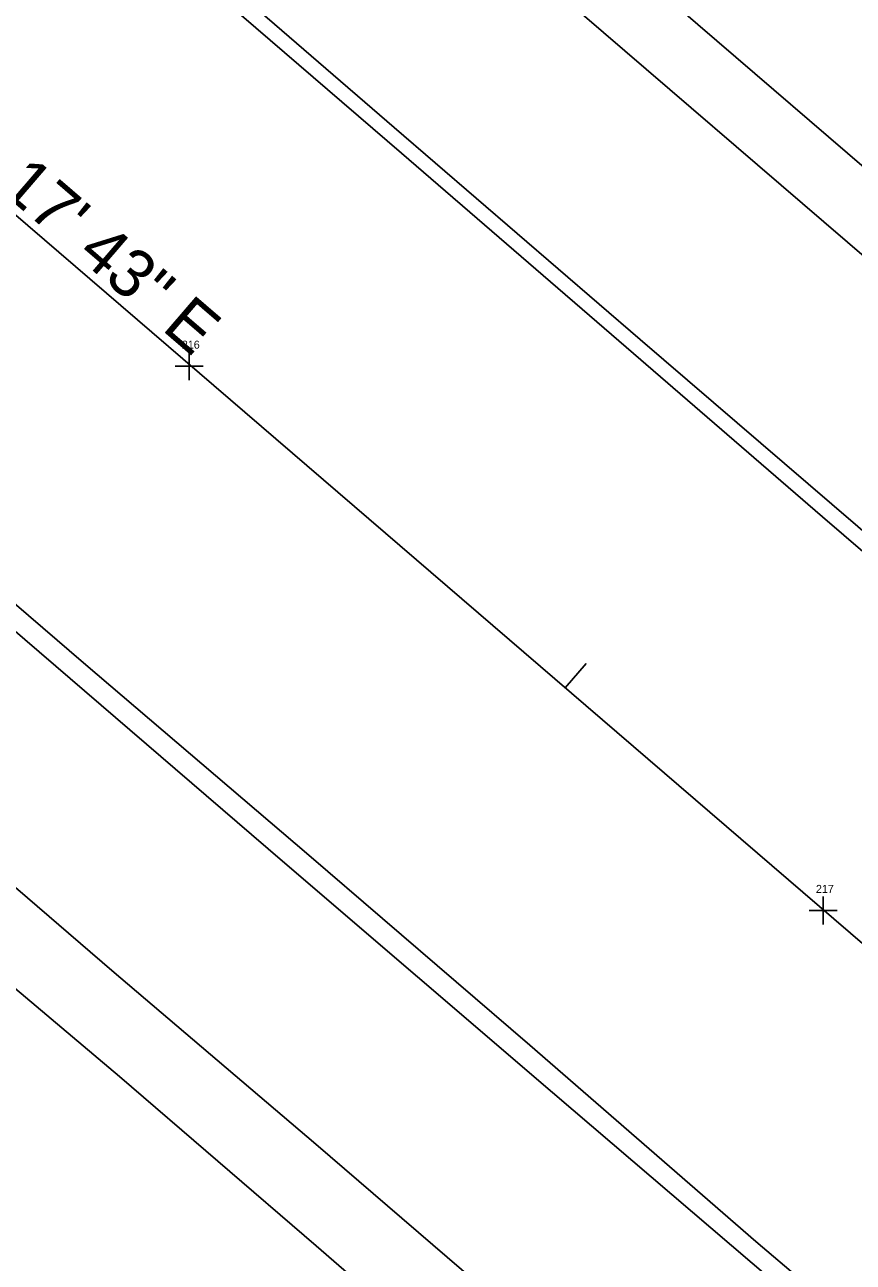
# Model space of a CAD drawing. Extents: x 2076109 to 2080761, y 592812 to 596750.
# Drawn here: x 2076795.1 to 2076898.6, y 596092.9 to 596247.5 of the extents above; entities that cross this region are included whole.
import ezdxf

# ---------------------------------------------------------------- set-up
doc = ezdxf.new("R2010")
doc.units = 0
for name, color, linetype in [('Default', 7, 'Continuous'), ('RD_EX_Misc', 7, 'Continuous'), ('RD_EX_Road', 7, 'Continuous'), ('RD_HC_Cl', 7, 'Continuous'), ('RD_HC_Data', 7, 'Continuous'), ('RD_HC_Data_Tic', 7, 'Continuous')]:
    doc.layers.add(name, color=color, linetype=linetype)

msp = doc.modelspace()

# ---------------------------------------------------------------- linework, layer by layer
at = {"layer": 'Default'}
for p, q in [((2076815.68, 596206.58), (2076815.68, 596203.08)), ((2076815.68, 596206.58), (2076815.68, 596203.08)), ((2076817.43, 596204.83), (2076813.93, 596204.83)), ((2076817.43, 596204.83), (2076813.93, 596204.83)), ((2076894.88, 596138.59), (2076894.88, 596135.09)), ((2076894.88, 596138.59), (2076894.88, 596135.09)), ((2076896.63, 596136.84), (2076893.13, 596136.84)), ((2076896.63, 596136.84), (2076893.13, 596136.84))]:
    msp.add_line(p, q, dxfattribs=at)
at = {"layer": 'RD_EX_Misc'}
for points in [[(2076810.47, 596295.64), (2076861.8, 596251.39), (2076900.57, 596218.06), (2076940.76, 596183.48), (2076983.39, 596147), (2077038.07, 596099.91), (2077086.97, 596057.78), (2077132.28, 596018.8), (2077181.85, 595976.05), (2077229.69, 595934.91), (2077274.19, 595896.66), (2077329.2, 595849.52), (2077358.6, 595824.22)], [(2076810.47, 596295.64), (2076861.8, 596251.39), (2076900.57, 596218.06), (2076940.76, 596183.48), (2076983.39, 596147), (2077038.07, 596099.91), (2077086.97, 596057.78), (2077132.28, 596018.8), (2077181.85, 595976.05), (2077229.69, 595934.91), (2077274.19, 595896.66), (2077329.2, 595849.52), (2077358.6, 595824.22)], [(2077334.93, 595810.96), (2077327.55, 595817.3), (2077300.53, 595840.37), (2077267.76, 595868.37), (2077240.07, 595892.05), (2077211.41, 595916.6), (2077178.43, 595944.97), (2077142.26, 595976.09), (2077108.47, 596005.28), (2077069.23, 596038.87), (2077039.16, 596064.68), (2077006.35, 596092.75), (2076967.21, 596126.45), (2076935.59, 596153.65), (2076905.14, 596179.73), (2076872.01, 596208.18), (2076841.3, 596234.65), (2076810.18, 596261.57), (2076792.25, 596277.09)], [(2077334.93, 595810.96), (2077327.55, 595817.3), (2077300.53, 595840.37), (2077267.76, 595868.37), (2077240.07, 595892.05), (2077211.41, 595916.6), (2077178.43, 595944.97), (2077142.26, 595976.09), (2077108.47, 596005.28), (2077069.23, 596038.87), (2077039.16, 596064.68), (2077006.35, 596092.75), (2076967.21, 596126.45), (2076935.59, 596153.65), (2076905.14, 596179.73), (2076872.01, 596208.18), (2076841.3, 596234.65), (2076810.18, 596261.57), (2076792.25, 596277.09)], [(2076740.94, 596217.33), (2076779.88, 596183.77), (2076827.32, 596143.01), (2076861.06, 596114.09), (2076898.34, 596082.26), (2076930.17, 596054.83), (2076977.99, 596013.66), (2077013.1, 595983.67), (2077050.75, 595951.15), (2077080.28, 595925.68), (2077141.22, 595873.03), (2077167.07, 595850.5), (2077217.75, 595806.94), (2077236.47, 595790.71), (2077261.03, 595769.53)], [(2076740.94, 596217.33), (2076779.88, 596183.77), (2076827.32, 596143.01), (2076861.06, 596114.09), (2076898.34, 596082.26), (2076930.17, 596054.83), (2076977.99, 596013.66), (2077013.1, 595983.67), (2077050.75, 595951.15), (2077080.28, 595925.68), (2077141.22, 595873.03), (2077167.07, 595850.5), (2077217.75, 595806.94), (2077236.47, 595790.71), (2077261.03, 595769.53)], [(2077238.94, 595757.09), (2077227.22, 595767.31), (2077200.97, 595789.86), (2077174.3, 595812.85), (2077143.56, 595839.45), (2077119.23, 595860.41), (2077093.27, 595882.76), (2077072.46, 595900.64), (2077047.17, 595922.37), (2077020.07, 595945.55), (2076995.16, 595967.19), (2076973.2, 595985.95), (2076950.94, 596005.11), (2076925.46, 596027.1), (2076903.87, 596045.6), (2076877.62, 596068.1), (2076855.08, 596087.36), (2076831.5, 596107.64), (2076806.02, 596129.35), (2076775.58, 596155.55), (2076743.51, 596183.09), (2076721.01, 596202.46)], [(2077238.94, 595757.09), (2077227.22, 595767.31), (2077200.97, 595789.86), (2077174.3, 595812.85), (2077143.56, 595839.45), (2077119.23, 595860.41), (2077093.27, 595882.76), (2077072.46, 595900.64), (2077047.17, 595922.37), (2077020.07, 595945.55), (2076995.16, 595967.19), (2076973.2, 595985.95), (2076950.94, 596005.11), (2076925.46, 596027.1), (2076903.87, 596045.6), (2076877.62, 596068.1), (2076855.08, 596087.36), (2076831.5, 596107.64), (2076806.02, 596129.35), (2076775.58, 596155.55), (2076743.51, 596183.09), (2076721.01, 596202.46)]]:
    msp.add_lwpolyline(points, dxfattribs=at)
at = {"layer": 'RD_EX_Road'}
for points in [[(2077309.59, 595877.22), (2077282.74, 595900.37), (2077256.36, 595923.26), (2077227.25, 595948.47), (2077198.79, 595972.87), (2077175.8, 595992.64), (2077153.37, 596012.36), (2077130.64, 596031.73), (2077105.62, 596053.51), (2077080.49, 596075.06), (2077051.54, 596099.91), (2077024.4, 596123.26), (2077002.19, 596142.32), (2076978.91, 596162.67), (2076952.21, 596185.24), (2076929.19, 596204.76), (2076902.69, 596227.39), (2076879.24, 596247.55), (2076859.1, 596264.86), (2076833.46, 596286.99), (2076816.41, 596301.99)], [(2077309.59, 595877.22), (2077282.74, 595900.37), (2077256.36, 595923.26), (2077227.25, 595948.47), (2077198.79, 595972.87), (2077175.8, 595992.64), (2077153.37, 596012.36), (2077130.64, 596031.73), (2077105.62, 596053.51), (2077080.49, 596075.06), (2077051.54, 596099.91), (2077024.4, 596123.26), (2077002.19, 596142.32), (2076978.91, 596162.67), (2076952.21, 596185.24), (2076929.19, 596204.76), (2076902.69, 596227.39), (2076879.24, 596247.55), (2076859.1, 596264.86), (2076833.46, 596286.99), (2076816.41, 596301.99)], [(2076790.96, 596275.94), (2076814.77, 596255.12), (2076842.21, 596231.47), (2076870.29, 596207.22), (2076894.79, 596186.02), (2076920.29, 596164.11), (2076947.36, 596141.05), (2076969.17, 596122), (2076994.72, 596100.04), (2077020.61, 596077.66), (2077049.58, 596053.31), (2077078.66, 596028.07), (2077094.19, 596014.5), (2077117.9, 595994.16), (2077143.78, 595971.83), (2077167.12, 595951.98), (2077186.93, 595934.87), (2077205.77, 595918.84), (2077227.43, 595900.11), (2077245.34, 595884.56), (2077262.98, 595869.29), (2077283.52, 595851.63), (2077302.45, 595835.44)], [(2076790.96, 596275.94), (2076814.77, 596255.12), (2076842.21, 596231.47), (2076870.29, 596207.22), (2076894.79, 596186.02), (2076920.29, 596164.11), (2076947.36, 596141.05), (2076969.17, 596122), (2076994.72, 596100.04), (2077020.61, 596077.66), (2077049.58, 596053.31), (2077078.66, 596028.07), (2077094.19, 596014.5), (2077117.9, 595994.16), (2077143.78, 595971.83), (2077167.12, 595951.98), (2077186.93, 595934.87), (2077205.77, 595918.84), (2077227.43, 595900.11), (2077245.34, 595884.56), (2077262.98, 595869.29), (2077283.52, 595851.63), (2077302.45, 595835.44)], [(2076745.26, 596217.16), (2076773.43, 596192.71), (2076802.46, 596167.8), (2076830.63, 596143.76), (2076858.22, 596120.02), (2076886.48, 596095.48), (2076909.61, 596075.82), (2076934.28, 596054.61), (2076959.06, 596033.36), (2076981.65, 596013.78), (2077008.04, 595991.17)], [(2076745.26, 596217.16), (2076773.43, 596192.71), (2076802.46, 596167.8), (2076830.63, 596143.76), (2076858.22, 596120.02), (2076886.48, 596095.48), (2076909.61, 596075.82), (2076934.28, 596054.61), (2076959.06, 596033.36), (2076981.65, 596013.78), (2077008.04, 595991.17)], [(2077010.62, 595940.91), (2076989.65, 595958.28), (2076967.68, 595977.24), (2076948.75, 595993.98), (2076926.34, 596013.36), (2076908.54, 596028.54), (2076891.07, 596043.63), (2076869.13, 596062.41), (2076850.42, 596078.6), (2076831.53, 596094.94), (2076806.96, 596116.11), (2076783.42, 596135.93), (2076762.1, 596154.8), (2076739.34, 596174.24), (2076719.05, 596191.54)], [(2077010.62, 595940.91), (2076989.65, 595958.28), (2076967.68, 595977.24), (2076948.75, 595993.98), (2076926.34, 596013.36), (2076908.54, 596028.54), (2076891.07, 596043.63), (2076869.13, 596062.41), (2076850.42, 596078.6), (2076831.53, 596094.94), (2076806.96, 596116.11), (2076783.42, 596135.93), (2076762.1, 596154.8), (2076739.34, 596174.24), (2076719.05, 596191.54)]]:
    msp.add_lwpolyline(points, dxfattribs=at)
at = {"layer": 'RD_HC_Cl'}
msp.add_line((2076186.59, 596746.26), (2077404.89, 595698.18), dxfattribs=at)
at = {"layer": 'RD_HC_Data_Tic'}
msp.add_line((2076862.65, 596164.67), (2076865.26, 596167.7), dxfattribs=at)
msp.add_line((2076862.65, 596164.67), (2076865.26, 596167.7), dxfattribs=at)

# ---------------------------------------------------------------- texts
at = {"layer": 'Default'}
for s, p in [('216', (2076814.76, 596207.03)), ('216', (2076814.76, 596207.03)), ('217', (2076893.98, 596139.04)), ('217', (2076893.98, 596139.04))]:
    msp.add_text(s, height=1, dxfattribs=at).set_placement(p)
at = {"layer": 'RD_HC_Data'}
msp.add_text('S 49%%d 17\' 43" E', height=6, rotation=319.2954, dxfattribs=at).set_placement((2076775.25, 596241.17))
msp.add_text('S 49%%d 17\' 43" E', height=6, rotation=319.2954, dxfattribs=at).set_placement((2076775.25, 596241.17))

doc.saveas('drawing.dxf')
